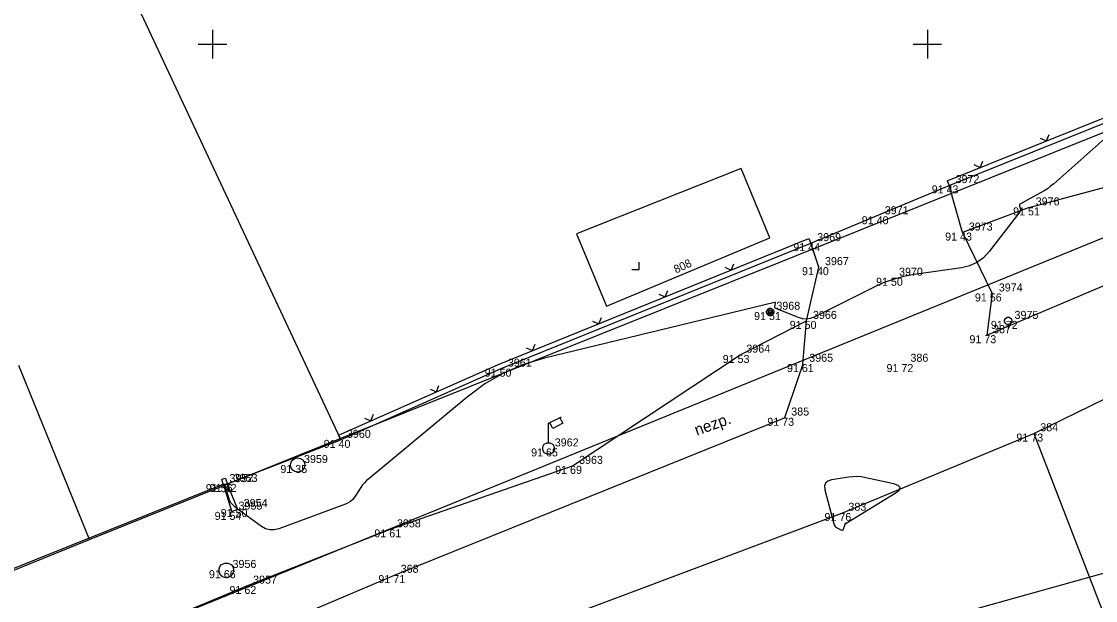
# Model space of a CAD drawing. Extents: x -711081 to -709338, y -1025122 to -1024092.
# Drawn here: x -710331.68 to -710294.12, y -1024744.46 to -1024724.21 of the extents above; entities that cross this region are included whole.
import ezdxf

# ---------------------------------------------------------------- set-up
doc = ezdxf.new("R2010")
doc.units = 0
for name, color, linetype in [('Ex_Minor Contours', 7, 'Continuous'), ('Z_betonova_konstrukce', 7, 'Continuous'), ('Z_body', 7, 'Continuous'), ('Z_body_cisla', 7, 'Continuous'), ('Z_body_vysky_redukovane', 7, 'Continuous'), ('Z_budova', 7, 'Continuous'), ('Z_hektometricka_sit', 7, 'Continuous'), ('Z_katastr_cisla_stavebni', 7, 'Continuous'), ('Z_katastr_hranice', 7, 'Continuous'), ('Z_katastr_hranice_katastralniho_uzemi', 7, 'Continuous'), ('Z_katastr_znacky_kultur', 7, 'Continuous'), ('Z_komunikace', 7, 'Continuous'), ('Z_komunikace_osa', 7, 'Continuous'), ('Z_ploty', 7, 'Continuous'), ('Z_ploty_znacky', 7, 'Continuous'), ('Z_popisy', 7, 'Continuous'), ('Z_rozhranni', 7, 'Continuous'), ('Z_site_kanalizace_znaky', 7, 'Continuous'), ('Z_site_plynovod_znaky', 7, 'Continuous'), ('Z_site_vo_znaky', 7, 'Continuous'), ('Z_sloupy', 7, 'Continuous'), ('Z_vstupy', 7, 'Continuous'), ('Z_zelen_jednotliva', 7, 'Continuous')]:
    doc.layers.add(name, color=color, linetype=linetype)

# ---------------------------------------------------------------- blocks, each defined once
blk = doc.blocks.new('POINT_DISPLAY')
blk.add_line((0, 0), (0, 0))
blk = doc.blocks.new('Z10001')
blk.add_circle((0, 0), 0.25)
blk = doc.blocks.new('Z212')
for p, q in [((-0.17, 0.17), (0, 0)), ((0, 0), (0.17, 0.17))]:
    blk.add_line(p, q)
blk = doc.blocks.new('Z614')
for p, q in [((-0.13, 0.03), (-0.1, 0.08)), ((-0.13, -0.03), (-0.13, 0.03)), ((-0.1, 0.08), (-0.08, 0.1)), ((-0.08, 0.1), (-0.03, 0.13)), ((-0.03, 0.13), (0.03, 0.13)), ((0.03, 0.13), (0.08, 0.1)), ((0.08, 0.1), (0.1, 0.08)), ((0.1, 0.08), (0.13, 0.03)), ((0.13, 0.03), (0.13, -0.03)), ((-0.1, -0.08), (-0.13, -0.03)), ((-0.08, -0.1), (-0.1, -0.08)), ((-0.03, -0.13), (-0.08, -0.1)), ((0.03, -0.13), (-0.03, -0.13)), ((0.08, -0.1), (0.03, -0.13)), ((0.1, -0.08), (0.08, -0.1)), ((0.13, -0.03), (0.1, -0.08))]:
    blk.add_line(p, q)
blk = doc.blocks.new('Z13')
for p, q in [((0, 0.88), (0.45, 1.1)), ((0, 0.2), (0, 0.88)), ((0.15, 0.7), (0.05, 0.9)), ((0.5, 0.88), (0.15, 0.7)), ((0.4, 1.07), (0.5, 0.88)), ((-0.2, 0.05), (-0.15, 0.15)), ((-0.2, -0.05), (-0.2, 0.05)), ((-0.15, 0.15), (-0.05, 0.2)), ((-0.05, 0.2), (0.05, 0.2)), ((0.05, 0.2), (0.15, 0.15)), ((0.15, 0.15), (0.2, 0.05)), ((0.2, 0.05), (0.2, -0.05)), ((-0.15, -0.15), (-0.2, -0.05)), ((-0.05, -0.2), (-0.15, -0.15)), ((0.05, -0.2), (-0.05, -0.2)), ((0.15, -0.15), (0.05, -0.2)), ((0.2, -0.05), (0.15, -0.15))]:
    blk.add_line(p, q)
blk = doc.blocks.new('Z620')
for p, q in [((-0.25, 0.05), (-0.23, 0.13)), ((-0.25, -0.05), (-0.25, 0.05)), ((-0.23, 0.13), (-0.17, 0.2)), ((-0.17, 0.2), (-0.05, 0.25)), ((-0.05, 0.25), (0.05, 0.25)), ((0.05, 0.25), (0.17, 0.2)), ((0.17, 0.2), (0.23, 0.13)), ((0.23, 0.13), (0.25, 0.05)), ((0.25, 0.05), (0.25, -0.05)), ((-0.2, -0.17), (-0.25, -0.05)), ((-0.13, -0.23), (-0.2, -0.17)), ((-0.05, -0.25), (-0.13, -0.23)), ((0.05, -0.25), (-0.05, -0.25)), ((0.13, -0.23), (0.05, -0.25)), ((0.2, -0.17), (0.13, -0.23)), ((0.25, -0.05), (0.2, -0.17))]:
    blk.add_line(p, q)
blk = doc.blocks.new('Z601')
for p, q in [((-0.13, 0.03), (-0.1, 0.08)), ((-0.13, -0.03), (-0.13, 0.03)), ((-0.1, 0.08), (-0.08, 0.1)), ((-0.08, 0.1), (-0.03, 0.13)), ((-0.08, 0.05), (-0.08, -0.05)), ((-0.03, 0.13), (0.03, 0.13)), ((-0.03, -0.08), (-0.03, 0.08)), ((-0.03, 0.08), (0.03, 0.08)), ((0.03, 0.13), (0.08, 0.1)), ((0.03, 0.08), (0.03, -0.08)), ((0.08, 0.1), (0.1, 0.08)), ((0.08, -0.05), (0.08, 0.05)), ((0.1, 0.08), (0.13, 0.03)), ((0.13, 0.03), (0.13, -0.03)), ((-0.1, -0.08), (-0.13, -0.03)), ((-0.08, -0.1), (-0.1, -0.08)), ((-0.08, -0.05), (-0.03, -0.08)), ((-0.03, -0.13), (-0.08, -0.1)), ((0.03, -0.13), (-0.03, -0.13)), ((0.03, -0.08), (0.08, -0.05)), ((0.08, -0.1), (0.03, -0.13)), ((0.1, -0.08), (0.08, -0.1)), ((0.13, -0.03), (0.1, -0.08))]:
    blk.add_line(p, q)

msp = doc.modelspace()

# ---------------------------------------------------------------- linework, layer by layer
at = {"layer": 'Ex_Minor Contours'}
msp.add_lwpolyline([(-710293.053, -1024727.65), (-710295.579, -1024729.882), (-710295.688, -1024729.973), (-710295.801, -1024730.057), (-710295.919, -1024730.135), (-710296.042, -1024730.206), (-710296.743, -1024730.588), (-710296.763, -1024730.603), (-710296.775, -1024730.62), (-710296.779, -1024730.641), (-710296.775, -1024730.665), (-710296.746, -1024730.768), (-710296.742, -1024730.794), (-710296.743, -1024730.818), (-710296.751, -1024730.841), (-710296.764, -1024730.862), (-710297.84, -1024732.258), (-710298.039, -1024732.473), (-710298.267, -1024732.639), (-710298.524, -1024732.756), (-710298.809, -1024732.823), (-710300.46, -1024733.062), (-710300.83, -1024733.13), (-710301.192, -1024733.228), (-710301.544, -1024733.354), (-710301.888, -1024733.509), (-710303.961, -1024734.545), (-710304.096, -1024734.597), (-710304.232, -1024734.618), (-710304.37, -1024734.608), (-710304.509, -1024734.567), (-710305.297, -1024734.247), (-710305.318, -1024734.235), (-710305.33, -1024734.22), (-710305.336, -1024734.2), (-710305.333, -1024734.177), (-710305.309, -1024734.076), (-710305.307, -1024734.055), (-710305.313, -1024734.041), (-710305.326, -1024734.036), (-710305.348, -1024734.038), (-710313.385, -1024735.983), (-710314.123, -1024736.206), (-710314.821, -1024736.507), (-710315.48, -1024736.887), (-710316.099, -1024737.345), (-710319.538, -1024740.199), (-710319.615, -1024740.267), (-710319.685, -1024740.341), (-710319.751, -1024740.419), (-710319.81, -1024740.502), (-710320.037, -1024740.846), (-710320.099, -1024740.926), (-710320.171, -1024740.993), (-710320.252, -1024741.047), (-710320.344, -1024741.089), (-710322.684, -1024741.951), (-710322.844, -1024741.99), (-710322.998, -1024741.99), (-710323.146, -1024741.949), (-710323.289, -1024741.868), (-710324.062, -1024741.309), (-710324.096, -1024741.284), (-710324.128, -1024741.258), (-710324.16, -1024741.231), (-710324.192, -1024741.203), (-710324.315, -1024741.09), (-710324.343, -1024741.06), (-710324.367, -1024741.027), (-710324.386, -1024740.992), (-710324.401, -1024740.953), (-710324.57, -1024740.386)], dxfattribs=at)
msp.add_lwpolyline([(-710302.298, -1024740.138), (-710302.448, -1024740.126), (-710302.599, -1024740.129), (-710302.75, -1024740.146), (-710303.354, -1024740.242), (-710303.482, -1024740.281), (-710303.562, -1024740.352), (-710303.595, -1024740.454), (-710303.58, -1024740.586), (-710303.27, -1024741.778), (-710303.257, -1024741.816), (-710303.236, -1024741.85), (-710303.209, -1024741.879), (-710303.176, -1024741.903), (-710303.021, -1024741.993), (-710302.99, -1024742.005), (-710302.966, -1024742.004), (-710302.946, -1024741.988), (-710302.932, -1024741.959), (-710302.866, -1024741.749), (-710302.865, -1024741.746), (-710302.863, -1024741.745), (-710302.861, -1024741.745), (-710302.858, -1024741.747), (-710302.847, -1024741.758), (-710302.845, -1024741.761), (-710302.842, -1024741.762), (-710302.839, -1024741.761), (-710302.835, -1024741.76), (-710301.122, -1024740.701), (-710300.987, -1024740.596), (-710300.951, -1024740.507), (-710301.015, -1024740.435), (-710301.177, -1024740.379), (-710302.149, -1024740.164)], close=True, dxfattribs=at)
at = {"layer": 'Z_betonova_konstrukce'}
for p, q in [((-710324.63, -1024740.39), (-710324.32, -1024741.36)), ((-710324.49, -1024740.38), (-710324.13, -1024741.26)), ((-710324.13, -1024741.26), (-710324.32, -1024741.36))]:
    msp.add_line(p, q, dxfattribs=at)
at = {"layer": 'Z_budova'}
for p, q in [((-710332.77, -1024743.66), (-710324.63, -1024740.39)), ((-710324.63, -1024740.39), (-710324.68, -1024740.22))]:
    msp.add_line(p, q, dxfattribs=at)
at = {"layer": 'Z_hektometricka_sit'}
for p, q in [((-710325, -1024724.5), (-710325, -1024725.5)), ((-710300, -1024724.5), (-710300, -1024725.5)), ((-710325.5, -1024725), (-710324.5, -1024725)), ((-710300.5, -1024725), (-710299.5, -1024725))]:
    msp.add_line(p, q, dxfattribs=at)
at = {"layer": 'Z_katastr_hranice'}
for p, q in [((-710346.66, -1024683.03), (-710320.54, -1024738.79)), ((-710320.54, -1024738.79), (-710292.89, -1024727.7)), ((-710306.51, -1024729.35), (-710312.27, -1024731.64)), ((-710305.51, -1024731.78), (-710306.51, -1024729.35)), ((-710312.27, -1024731.64), (-710311.22, -1024734.16)), ((-710311.22, -1024734.16), (-710305.51, -1024731.78)), ((-710331.38, -1024737.22), (-710331.78, -1024736.24)), ((-710329.3, -1024742.33), (-710331.38, -1024737.22)), ((-710324.64, -1024740.45), (-710320.54, -1024738.79)), ((-710329.3, -1024742.33), (-710324.64, -1024740.45)), ((-710348.48, -1024750.08), (-710329.3, -1024742.33)), ((-710288.46, -1024742.02), (-710303.04, -1024746.07))]:
    msp.add_line(p, q, dxfattribs=at)
at = {"layer": 'Z_katastr_hranice_katastralniho_uzemi'}
msp.add_line((-710277.4, -1024725.07), (-710392.31, -1024771.94), dxfattribs=at)
msp.add_line((-710277.4, -1024725.07), (-710392.31, -1024771.94), dxfattribs=at)
at = {"layer": 'Z_katastr_znacky_kultur'}
for p, q in [((-710310.33, -1024732.88), (-710310.08, -1024732.88)), ((-710310.08, -1024732.88), (-710310.08, -1024732.63))]:
    msp.add_line(p, q, dxfattribs=at)
at = {"layer": 'Z_komunikace'}
for p, q in [((-710298.77, -1024731.59), (-710299.24, -1024729.94)), ((-710298.77, -1024731.59), (-710297.73, -1024733.72)), ((-710303.8, -1024732.8), (-710304.08, -1024731.96)), ((-710297.92, -1024735.18), (-710291.66, -1024732.52)), ((-710304.23, -1024734.68), (-710303.8, -1024732.8)), ((-710297.73, -1024733.72), (-710297.92, -1024735.18)), ((-710304.35, -1024736.19), (-710304.23, -1024734.68)), ((-710304.35, -1024736.19), (-710304.99, -1024738.07)), ((-710318.64, -1024743.57), (-710304.99, -1024738.07)), ((-710331.18, -1024748.89), (-710318.64, -1024743.57))]:
    msp.add_line(p, q, dxfattribs=at)
at = {"layer": 'Z_komunikace_osa'}
for p, q in [((-710296.28, -1024738.62), (-710290.38, -1024735.74)), ((-710302.99, -1024741.4), (-710296.28, -1024738.62)), ((-710296.28, -1024738.62), (-710292.63, -1024748.02)), ((-710317.1, -1024746.7), (-710302.99, -1024741.4))]:
    msp.add_line(p, q, dxfattribs=at)
at = {"layer": 'Z_ploty'}
for p, q in [((-710299.31, -1024729.78), (-710293.27, -1024727.35)), ((-710299.24, -1024729.94), (-710293.2, -1024727.51)), ((-710299.31, -1024729.78), (-710299.24, -1024729.94)), ((-710314.97, -1024736.19), (-710304.15, -1024731.8)), ((-710304.15, -1024731.8), (-710304.08, -1024731.96)), ((-710314.9, -1024736.35), (-710304.08, -1024731.96)), ((-710320.6, -1024738.68), (-710314.97, -1024736.19)), ((-710320.53, -1024738.84), (-710314.9, -1024736.35)), ((-710320.6, -1024738.68), (-710320.53, -1024738.84)), ((-710324.68, -1024740.22), (-710324.55, -1024740.18)), ((-710324.63, -1024740.39), (-710324.49, -1024740.38)), ((-710324.55, -1024740.18), (-710324.49, -1024740.38))]:
    msp.add_line(p, q, dxfattribs=at)
at = {"layer": 'Z_rozhranni'}
for p, q in [((-710296.44, -1024730.71), (-710290.68, -1024729.17)), ((-710296.44, -1024730.71), (-710298.77, -1024731.59)), ((-710306.55, -1024735.87), (-710304.23, -1024734.68)), ((-710312.41, -1024739.75), (-710306.55, -1024735.87)), ((-710318.78, -1024741.97), (-710312.41, -1024739.75)), ((-710323.8, -1024743.95), (-710318.78, -1024741.97)), ((-710332.24, -1024747.44), (-710323.8, -1024743.95))]:
    msp.add_line(p, q, dxfattribs=at)
at = {"layer": 'Z_vstupy'}
for p, q in [((-710304.08, -1024731.96), (-710299.24, -1024729.94)), ((-710324.49, -1024740.38), (-710320.53, -1024738.84))]:
    msp.add_line(p, q, dxfattribs=at)

# ---------------------------------------------------------------- block references
at = {"layer": 'Z_body'}
for p in [(-710299.24, -1024729.94), (-710296.44, -1024730.71), (-710301.71, -1024731.02), (-710298.77, -1024731.59), (-710304.08, -1024731.96), (-710303.8, -1024732.8), (-710301.21, -1024733.17), (-710297.73, -1024733.72), (-710305.5, -1024734.37), (-710304.23, -1024734.68), (-710297.17, -1024734.68), (-710297.92, -1024735.18), (-710306.55, -1024735.87), (-710314.9, -1024736.35), (-710304.35, -1024736.19), (-710300.82, -1024736.19), (-710304.99, -1024738.07), (-710296.28, -1024738.62), (-710320.53, -1024738.84), (-710313.25, -1024739.14), (-710322.02, -1024739.72), (-710312.41, -1024739.75), (-710324.63, -1024740.39), (-710324.49, -1024740.38), (-710324.32, -1024741.36), (-710324.13, -1024741.26), (-710302.99, -1024741.4), (-710318.78, -1024741.97), (-710324.52, -1024743.4), (-710318.64, -1024743.57), (-710323.8, -1024743.95)]:
    msp.add_blockref('POINT_DISPLAY', p, dxfattribs=at)
at = {"layer": 'Z_ploty_znacky'}
for p, rotation in [((-710295.83, -1024728.38), 21.9), ((-710298.15, -1024729.31), 21.9), ((-710306.86, -1024732.9), 22.1), ((-710309.17, -1024733.84), 22.1), ((-710311.49, -1024734.78), 22.1), ((-710313.81, -1024735.72), 22.1), ((-710317.17, -1024737.16), 23.9), ((-710319.46, -1024738.17), 23.9)]:
    msp.add_blockref('Z212', p, dxfattribs=dict(at, rotation=rotation))
at = {"layer": 'Z_site_kanalizace_znaky'}
msp.add_blockref('Z620', (-710324.52, -1024743.4), dxfattribs=at)
at = {"layer": 'Z_site_plynovod_znaky'}
msp.add_blockref('Z614', (-710297.17, -1024734.68), dxfattribs=at)
at = {"layer": 'Z_site_vo_znaky'}
msp.add_blockref('Z13', (-710313.25, -1024739.14), dxfattribs=at)
at = {"layer": 'Z_sloupy'}
msp.add_blockref('Z601', (-710305.5, -1024734.37), dxfattribs=at)
at = {"layer": 'Z_zelen_jednotliva'}
msp.add_blockref('Z10001', (-710322.02, -1024739.72), dxfattribs=at)

# ---------------------------------------------------------------- texts
at = {"layer": 'Z_body_cisla'}
for s, p in [('3972', (-710299.01, -1024729.86)), ('3976', (-710296.21, -1024730.64)), ('3971', (-710301.49, -1024730.95)), ('3973', (-710298.55, -1024731.52)), ('3969', (-710303.85, -1024731.89)), ('3967', (-710303.58, -1024732.73)), ('3970', (-710300.99, -1024733.1)), ('3974', (-710297.5, -1024733.65)), ('3968', (-710305.28, -1024734.29)), ('3966', (-710304, -1024734.61)), ('3975', (-710296.95, -1024734.61)), ('387', (-710297.7, -1024735.11)), ('3964', (-710306.33, -1024735.79)), ('3961', (-710314.67, -1024736.28)), ('3965', (-710304.13, -1024736.11)), ('386', (-710300.59, -1024736.11)), ('385', (-710304.76, -1024737.99)), ('3960', (-710320.3, -1024738.77)), ('384', (-710296.05, -1024738.54)), ('3962', (-710313.03, -1024739.07)), ('3959', (-710321.8, -1024739.65)), ('3963', (-710312.18, -1024739.68)), ('3952', (-710324.41, -1024740.32)), ('3953', (-710324.26, -1024740.31)), ('3955', (-710324.09, -1024741.28)), ('3954', (-710323.91, -1024741.19)), ('383', (-710302.76, -1024741.32)), ('3958', (-710318.55, -1024741.9)), ('3956', (-710324.3, -1024743.32)), ('368', (-710318.42, -1024743.49)), ('3957', (-710323.58, -1024743.87))]:
    msp.add_text(s, height=0.28, dxfattribs=at).set_placement(p)
at = {"layer": 'Z_body_vysky_redukovane'}
for s, p in [('91 43', (-710299.847, -1024730.22)), ('91 51', (-710297, -1024730.99)), ('91 40', (-710302.293, -1024731.3)), ('91 43', (-710299.377, -1024731.87)), ('91 44', (-710304.687, -1024732.24)), ('91 40', (-710304.383, -1024733.08)), ('91 50', (-710301.793, -1024733.45)), ('91 56', (-710298.337, -1024734)), ('91 51', (-710306.06, -1024734.65)), ('91 50', (-710304.813, -1024734.96)), ('91 72', (-710297.777, -1024734.96)), ('91 73', (-710298.527, -1024735.46)), ('91 53', (-710307.157, -1024736.15)), ('91 50', (-710315.483, -1024736.63)), ('91 61', (-710304.91, -1024736.47)), ('91 72', (-710301.427, -1024736.47)), ('91 73', (-710305.597, -1024738.35)), ('91 73', (-710296.887, -1024738.9)), ('91 40', (-710321.113, -1024739.12)), ('91 65', (-710313.857, -1024739.42)), ('91 35', (-710322.627, -1024740)), ('91 69', (-710313.017, -1024740.03)), ('91 56', (-710325.237, -1024740.67)), ('91 42', (-710325.097, -1024740.66)), ('91 50', (-710324.713, -1024741.54)), ('91 54', (-710324.927, -1024741.64)), ('91 76', (-710303.597, -1024741.68)), ('91 61', (-710319.34, -1024742.25)), ('91 66', (-710325.127, -1024743.68)), ('91 71', (-710319.2, -1024743.85)), ('91 62', (-710324.407, -1024744.23))]:
    msp.add_text(s, height=0.28, dxfattribs=at).set_placement(p)
at = {"layer": 'Z_katastr_cisla_stavebni'}
msp.add_text('808', height=0.2847, rotation=25, dxfattribs=at).set_placement((-710308.789, -1024733.026))
at = {"layer": 'Z_popisy'}
msp.add_text('nezp.', height=0.4, rotation=19.8, dxfattribs=at).set_placement((-710308.06, -1024738.7))

doc.saveas('drawing.dxf')
